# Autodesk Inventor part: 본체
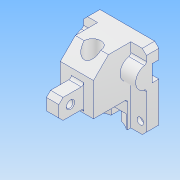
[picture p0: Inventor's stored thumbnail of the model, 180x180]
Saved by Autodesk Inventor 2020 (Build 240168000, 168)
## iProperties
Created: 2022-08
Part Number: 본체
Material: 알루미늄 6061
Document SubType Name: Modeling
Designer: user
Density: 2.7 g/cm^3
Appearance: 알루미늄 - 평지
Mass: 503.935 g
Surface Area: 335.341 cm^2
Volume: 186.643 cm^3
Author: user
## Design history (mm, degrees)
sketch "스케치1"
  geometry: L1 (38, 45)-(-38, 45); L2 (-38, 45)-(-38, -45); L3 (-38, -45)-(38, -45); L4 (38, -45)-(38, 45); L5 (38, 45)-(-38, -45); L6 (-38, 45)-(38, -45); 1 further point
  constraints: 12 end point, 2 midpoint, 2 parallel, 1 horizontal, 1 perpendicular
  dimensions: "d0" = 76 distance of L3.end L2.end; "d1" = 90 distance of L2.end L1.end
extrude "돌출1" new body sketch "스케치1" distance "d2" = 15; taper "d3" = 0 deg
sketch "스케치2"
  geometry: L1 (-38, -45)-(38, -45) reference; L2 (38, 45)-(-38, 45) reference; L3 (-20.765, 45)-(19.235, 45); L4 (19.235, 45)-(19.235, -13); L5 (19.235, -13)-(-20.765, -13); L6 (-20.765, -13)-(-20.765, 45); L7 (38, -45)-(38, 45) reference; 2 further points
  constraints: 8 end point, 2 parallel, 1 horizontal, 1 midpoint, 1 perpendicular, 1 point on line, 1 vertical alignment
  dimensions: "d4" = 32 distance between parallel lines of L1 L5; "d6" = 40 distance between parallel lines of L6 L4; "d7" = 18.76519 distance between parallel lines of L7 L4
extrude "돌출2" join sketch "스케치2" distance "d8" = 45; taper "d9" = 0 deg
sketch "스케치3"
  geometry: L1 (-20.765, -13)-(19.235, -13) reference; L2 (-7.5, 16)-(7.5, 16); L3 (7.5, 16)-(7.5, -8); L4 (7.5, -8)-(-7.5, -8); L5 (-7.5, -8)-(-7.5, 16); 2 further points
  constraints: 8 end point, 2 parallel, 1 horizontal, 1 midpoint, 1 perpendicular, 1 vertical alignment
  dimensions: "d10" = 5 distance between parallel lines of L1 L4; "d11" = 24 distance of L4.end L2.start; "d12" = 15 distance of L2.start L2.end
extrude "돌출3" join sketch "스케치3" distance "d13" = 30; taper "d14" = 0 deg
sketch "스케치4"
  geometry: L1 (15, 90)-(15, 0) reference; L2 (0, 90)-(15, 90) reference; C1 r 13 at (15, 63); 1 further point
  constraints: 1 centre point, 1 point on line
  dimensions: "d15" = 26 diameter of C1; "d16" = 27 distance from line of L2 C1.centre
extrude "돌출4" join sketch "스케치4" distance "d17" = 76; taper "d18" = 0 deg
sketch "스케치5"
  geometry: L1 (0, 90)-(0, 0) reference; L2 (8, 73)-(-8, 73); L3 (-8, 73)-(-8, 53); L4 (-8, 53)-(8, 53); L5 (8, 53)-(8, 73); L6 (8, 73)-(-8, 53); L7 (-8, 73)-(8, 53); A1 r 13 centre (15, 63) between (15, 50) and (15, 76) reference; 3 further points
  constraints: 12 end point, 3 midpoint, 2 parallel, 1 horizontal, 1 horizontal alignment, 1 perpendicular, 1 point on line
  dimensions: "d19" = 16 distance of L4.end L3.end; "d20" = 20 distance of L3.end L2.end
extrude "돌출5" cut sketch "스케치5" extent not by distance; stored distance "d21" = 0; taper "d22" = 0 deg
sketch "스케치6"
  geometry: L1 (-38, -45)-(38, -45) reference; L2 (19.235, -13)-(-20.765, -13); L3 (-20.765, -13)-(-20.765, -45); L4 (-20.765, -45)-(19.235, -45); L5 (19.235, -45)-(19.235, -13); 1 further point
  constraints: 8 end point, 2 parallel, 1 horizontal, 1 perpendicular, 1 point on line
extrude "돌출6" join sketch "스케치6" distance "d23" = 4; taper "d24" = 0 deg
sketch "스케치7"
  geometry: L1 (44, 19)-(32, 19); L2 (32, 19)-(32, -19); L3 (32, -19)-(44, -19); L4 (44, -19)-(44, 19); L5 (44, 19)-(32, -19); L6 (32, 19)-(44, -19); 1 further point
  constraints: 12 end point, 2 midpoint, 2 parallel, 1 horizontal, 1 perpendicular
  dimensions: "d25" = 12 distance of L3.end L2.end; "d26" = 38 distance of L2.end L1.end
extrude "돌출7" cut sketch "스케치7" distance "d27" = 16; taper "d28" = 0 deg
sketch "스케치8"
  geometry: C1 r 29 at (-38, 42); 1 further point
  constraints: 1 centre point, 1 vertical alignment
  dimensions: "d29" = 58 diameter of C1; "d30" = 42 distance of point (-38, 0) C1.centre
extrude "돌출8" cut sketch "스케치8" distance "d31" = 16; taper "d32" = 0 deg
sketch "스케치9"
  geometry: L1 (26.765, -60)-(14.765, -60) reference; C1 r 14.5 at (20.765, -18); 2 further points
  constraints: 1 centre point, 1 midpoint, 1 vertical alignment
  dimensions: "d33" = 29 diameter of C1; "d34" = 42 distance from line of L1 C1.centre
extrude "돌출9" cut sketch "스케치9" distance "d35" = 7; taper "d36" = 0 deg
sketch "스케치10"
  geometry: L1 (6, -42)-(-6, -42) reference; C1 r 14.5 at (0, 0); C2 r 10 at (0, 0); 2 further points
  constraints: 2 centre point, 1 coincident, 1 midpoint, 1 vertical alignment
  dimensions: "d37" = 20 diameter of C2; "d74" = 42 distance from line of L1 C1.centre
extrude "돌출10" cut sketch "스케치10" extent not by distance; stored distance "d38" = 0; taper "d39" = 0 deg
chamfer "모따기1" distance "d40" = 18; stored, may be unused: second distance "d41" = 2, angle "d42" = 45 deg
chamfer "모따기2" distance "d43" = 5; stored, may be unused: second distance "d44" = 2, angle "d45" = 45 deg
fillet "모깎기1" dims "d46" = 3
fillet "모깎기2" dims "d47" = 3
sketch "스케치11"
  geometry: L1 (-3, 90)-(11, 90) reference; L2 (-13, 22)-(-13, 60) reference; L3 (-13, 41)-(45, 41); L4 (45, 15)-(45, 42) reference; C1 r 4 at (4, 76); 2 further points
  constraints: 2 end point, 2 midpoint, 1 centre point, 1 horizontal, 1 point on line, 1 vertical alignment
  dimensions: "d48" = 8 diameter of C1; "d49" = 35 distance from line of C1.centre L3
extrude "돌출11" cut sketch "스케치11" extent not by distance; stored distance "d50" = 7.5; taper "d51" = 0 deg
chamfer "모따기3" distance "d52" = 1; stored, may be unused: second distance "d53" = 2, angle "d54" = 45 deg
chamfer "모따기4" distance "d55" = 1; stored, may be unused: second distance "d56" = 2, angle "d57" = 45 deg
sketch "스케치12"
  geometry: L1 (7, 32)-(45, 32) reference; L2 (45, 72)-(45, 32) reference; 2 further points
  constraints: 1 other
  dimensions: "d58" = 26 distance from line of point (27, 58) L1; "d59" = 18 distance from line of L2 point (27, 58)
feature "엠보싱1" sketch "스케치12" dims "d0" = 76, "d1" = 90, "d60" = 0.5, "d61" = 0
chamfer "모따기5" distance "d62" = 5; stored, may be unused: second distance "d63" = 2, angle "d64" = 45 deg
sketch "스케치13"
  geometry: L1 (-33, -45)-(-20.765, -45) reference; L2 (-38, 2.284)-(-20.765, 2.284) reference; 4 further points
  constraints: 1 horizontal alignment, 1 midpoint, 1 vertical alignment
  dimensions: "d65" = 13 distance from line of L1 point (-29.383, -32); "d66" = 60 distance of point (-29.383, -32) point (30.617, -32)
hole "구멍1" sketch "스케치13" at (-29.383, -32), (30.617, -32) diameter "d67" = 4.5; stored, may be unused: countersink angle "d71" = 90 deg, drill point angle "d73" = 118 deg; dims "d68" = 10, "d69" = 8, "d70" = 4.4, "d72" = 12
node "솔리드1"
feature "A9D066F2-1C7D-4E18-AEED-F7BC21143FA4" dims "d67" = 4.5, "d68" = 10, "d69" = 8, "d70" = 4.4, "d71" = 90 deg, "d72" = 12, "d73" = 118 deg
